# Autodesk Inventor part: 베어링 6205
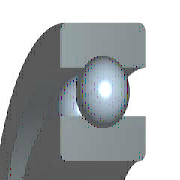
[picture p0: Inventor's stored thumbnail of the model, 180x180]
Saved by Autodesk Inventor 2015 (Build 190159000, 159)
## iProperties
Company: 한국ATC센터
IsCustomPart: 1
Created: 2009-02
Part Number: 베어링 6205
Material: Steel, Mild
Description: 깊은 그루브 볼 베어링
Document SubType Name: Modeling
Standard: KS B 2023
Designer: KYOUNG IL JANG
Standards Organization: KS
Language: ko-KR
Size Designation: 6205 - 25 x 52 x 15
Categories: <MemberInstance><Categories><Category DisplayName="샤프트 부품" InternalName="7f7aeb1f-a693-4053-b835-cee3144e0d98" Mnemonic="SHFT"><Category DisplayName="베어링" Inter
Density: 1 g/cm^3
Appearance: Steel
Author: KYOUNG IL JANG
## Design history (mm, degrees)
revolve "본체" stored, may be unused: angle "d6" = 90 deg
revolve "볼" stored, may be unused: angle "d7" = 90 deg
pattern_circular "IDS_ARRAYBALL[SIMPL:T]" dims angle "d3" = 360 deg
body "Solid1"
sketch "스케치" dims "d0" = 7.02 (= -0.26 x WD + 0.26 x BD)
  geometry: L1 (3.99, 19.25)-(11.01, 19.25); L2 (7.5, 19.25)-(7.5, 15.74); L3 (7.5, 19.25)-(7.5, 22.76); L4 (4.892, 16.901)-(0, 16.901); L5 (0, 12.5)-(15, 12.5); L6 (4.892, 21.599)-(0, 21.599); L7 (0, 26)-(15, 26); L8 (15, 12.5)-(15, 16.901); L9 (10.108, 16.901)-(15, 16.901); L10 (10.108, 21.599)-(15, 21.599); L11 (15, 26)-(15, 21.599); L12 (-1.4, 0)-(8.4, 0) reference; L13 (0, -0.3)-(0, 5.3) reference
  constraints: 22 end point, 4 point on line, 2 collinear, 2 perpendicular, 2 symmetric about line, 1 midpoint, 1 parallel, 14 other
  dimensions: "d9" = 25 diameter of L5 L12 (= WD); "d11" = 52 diameter of L7 L12 (= BD); "d12" = 15 distance between parallel lines of L8 L13 (= KB); "d13" = 33.802 diameter of L9 L12 (= 0.326 x BD + 0.674 x WD)
fillet "모깎기1" dims "d1" = 1 (= KRS)
other parameters: "WD" = 25 [user parameter; used in 5 equation terms], "BD" = 52 [user parameter; used in 5 equation terms], "KB" = 15 [user parameter; used in 1 equation term], "KRS" = 1 [user parameter; used in 1 equation term], "d4" = 0, "d5" = 0, "d8" = 0, "d14" = 0, "d15" = 0, "BBA" = 0 [user parameter], "BC0" = 7800000 [user parameter], "BC" = 1.4e+07 [user parameter], "BR" = 26 (= 0.5 x BD) [user parameter], "WR" = 12.5 (= 0.5 x WD) [user parameter]
